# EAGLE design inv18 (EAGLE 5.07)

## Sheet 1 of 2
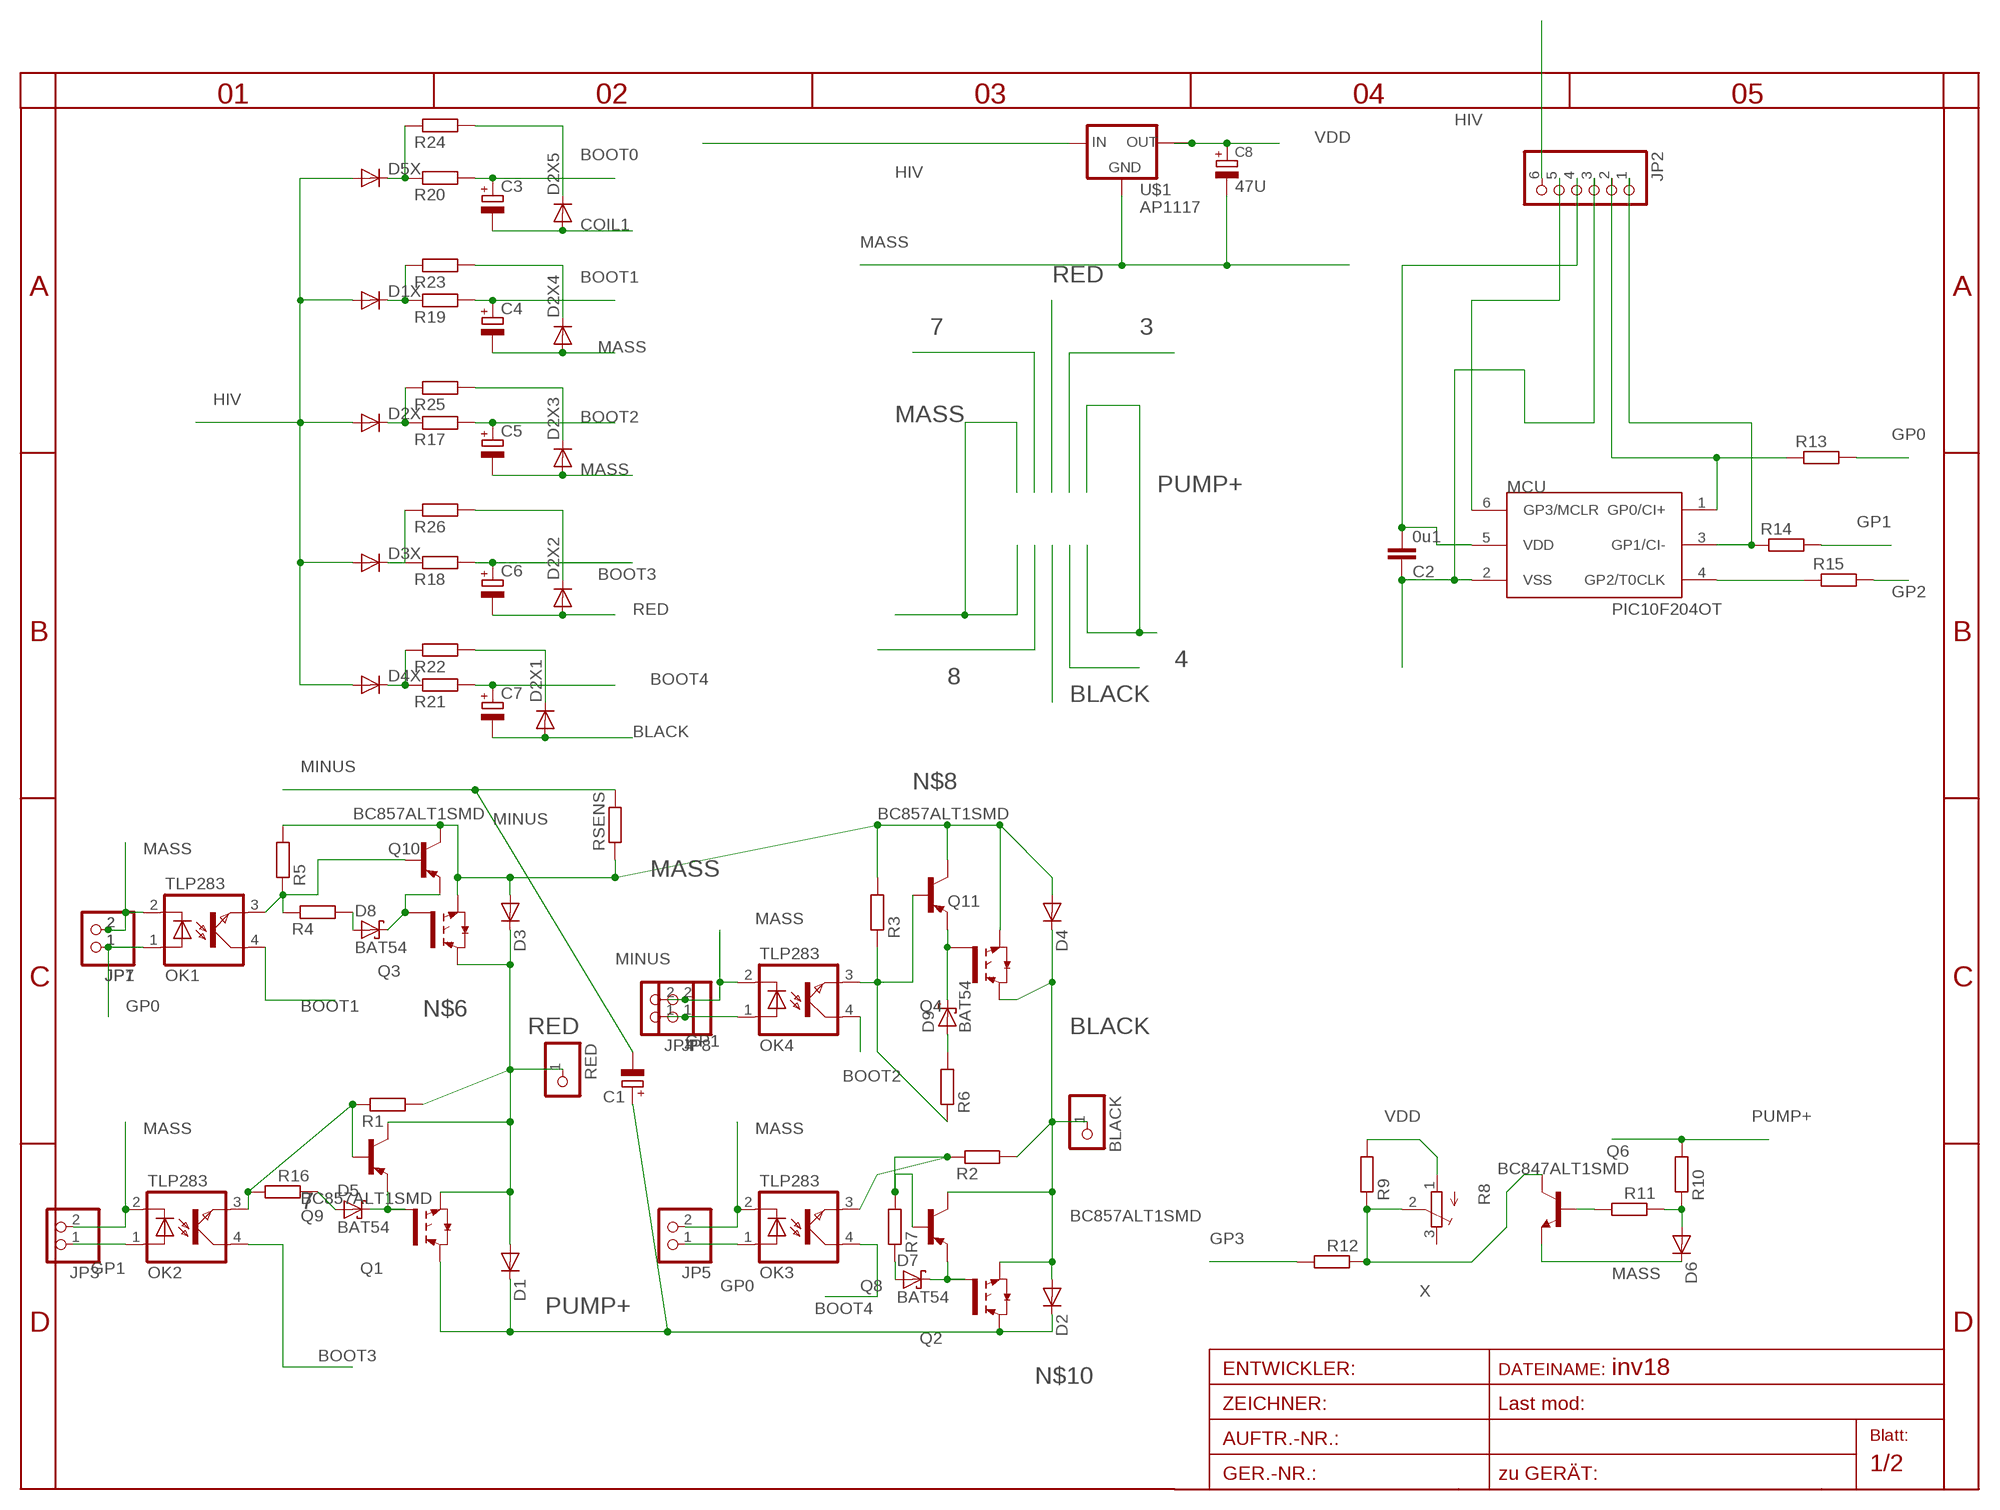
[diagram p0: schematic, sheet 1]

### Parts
BLACK  PINHD-1X14.5MM  [1X4MM5]
C1  CPOL-EUE5-13  [E5-13]
C2  0u1  C-EUC0805  [C0805]
C3  CPOL-EUC  [PANASONIC_C]
C4  CPOL-EUC  [PANASONIC_C]
C5  CPOL-EUC  [PANASONIC_C]
C6  CPOL-EUC  [PANASONIC_C]
C7  CPOL-EUC  [PANASONIC_C]
C8  47U  CPOL-EUC  [PANASONIC_C]
D1  DIODE-SMC  [SMC]
D1X  DIODE-SMA-DO214  [SMA-DO214AC]
D2  DIODE-SMC  [SMC]
D2X  DIODE-SMA-DO214  [SMA-DO214AC]
D2X1  DIODE-MINIMELF  [MINIMELF]
D2X2  DIODE-MINIMELF  [MINIMELF]
D2X3  DIODE-MINIMELF  [MINIMELF]
D2X4  DIODE-MINIMELF  [MINIMELF]
D2X5  DIODE-MINIMELF  [MINIMELF]
D3  DIODE-SMC  [SMC]
D3X  DIODE-SMA-DO214  [SMA-DO214AC]
D4  DIODE-SMC  [SMC]
D4X  DIODE-SMA-DO214  [SMA-DO214AC]
D5  BAT54  [SOT23]
D5X  DIODE-SMA-DO214  [SMA-DO214AC]
D6  DIODE-MINIMELF  [MINIMELF]
D7  BAT54  [SOT23]
D8  BAT54  [SOT23]
D9  BAT54  [SOT23]
JP1  PINHD-1X2STR  [1X02]
JP2  PINHD-1X6  [1X06BOX]
JP3  PINHD-1X2STR  [1X02]
JP4  PINHD-1X2STR  [1X02]
JP5  PINHD-1X2STR  [1X02]
JP7  PINHD-1X2STR  [1X02]
JP8  PINHD-1X2STR  [1X02]
MCU  PIC10F204OT  [SOT23-6]
OK1  TLP283  [MINI-FLAT-4]
OK2  TLP283  [MINI-FLAT-4]
OK3  TLP283  [MINI-FLAT-4]
OK4  TLP283  [MINI-FLAT-4]
Q1  IRG4BC15UD-S  [D2PACK]
Q2  IRG4BC15UD-S  [D2PACK]
Q3  IRG4BC15UD-S  [D2PACK]
Q4  IRG4BC15UD-S  [D2PACK]
Q6  BC847ALT1SMD  [SOT23]
Q8  BC857ALT1SMD  [SOT23-BEC]
Q9  BC857ALT1SMD  [SOT23-BEC]
Q10  BC857ALT1SMD  [SOT23-BEC]
Q11  BC857ALT1SMD  [SOT23-BEC]
R1  R-EU_R1206  [R1206]
R2  R-EU_R1206  [R1206]
R3  R-EU_R1206  [R1206]
R4  R-EU_R1206  [R1206]
R5  R-EU_R1206  [R1206]
R6  R-EU_R1206  [R1206]
R7  R-EU_R1206  [R1206]
R8  TRIM_EU-3223W  [3223W]
R9  R-EU_R1206  [R1206]
R10  R-EU_R1206  [R1206]
R11  R-EU_R1206  [R1206]
R12  R-EU_R1206  [R1206]
R13  R-EU_0207/25  [0207/25]
R14  R-EU_0207/25  [0207/25]
R15  R-EU_0207/25  [0207/25]
R16  R-EU_R1206  [R1206]
R17  R-EU_R1206  [R1206]
R18  R-EU_R1206  [R1206]
R19  R-EU_R1206  [R1206]
R20  R-EU_R1206  [R1206]
R21  R-EU_R1206  [R1206]
R22  R-EU_R1206  [R1206]
R23  R-EU_R1206  [R1206]
R24  R-EU_R1206  [R1206]
R25  R-EU_R1206  [R1206]
R26  R-EU_R1206  [R1206]
RED  PINHD-1X14.5MM  [1X4MM5]
RSENS  R-EU_CERAM50  [CERAM50]
U$1  AP1117  [SOT223]

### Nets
3: OK1.3(EMIT) Q10.B R4.1 R5.1
4: OK3.3(EMIT) Q8.B R2.1 R7.2
7: OK2.3(EMIT) Q9.B R1.1 R16.2
BLACK: BLACK.1 C7.- D2.A D2X1.A D4.C Q2.3(E) Q4.2(C) Q8.C R2.2
BOOT0: C3.+ R20.2 ; also sheet 2
BOOT1: C4.+ OK1.4(COL) R19.2
BOOT2: C5.+ OK4.4(COL) R17.2
BOOT3: C6.+ OK2.4(COL) R18.2
BOOT4: C7.+ OK3.4(COL) R21.2
COIL1: C3.- D2X5.A ; also sheet 2
GP0: JP1.1 JP5.1 JP7.1 OK1.1(A) OK3.1(A) R13.2
GP0I: JP2.2 MCU.1(GP0/CI+) R13.1
GP1: JP3.1 JP4.1 JP8.1 OK2.1(A) OK4.1(A) R14.2
GP1I: JP2.1 MCU.3(GP1/CI-) R14.1
GP2: R15.2 ; also sheet 2
GP2I: MCU.4(GP2/T0CLK) R15.1
GP3: JP2.5 MCU.6(GP3/MCLR) R12.2
HIV: D1X.A D2X.A D3X.A D4X.A D5X.A JP2.6 U$1.3(IN) ; also sheet 2
MASS: C2.1 C4.- C5.- C8.- D2X3.A D2X4.A D3.A D4.A D6.C JP1.2 JP2.3 JP3.2 JP4.2 JP5.2 JP7.2 JP8.2 MCU.2(VSS) OK1.2(C) OK2.2(C) OK3.2(C) OK4.2(C) Q3.3(E) Q4.3(E) Q6.2(E) Q10.C Q11.C R3.2 R5.2 RSENS.1 U$1.1(GND) ; also sheet 2
MINUS: C1.- RSENS.2 ; also sheet 2
N$2: D8.1(A) R4.2
N$4: D6.A R10.1 R11.1
N$5: Q6.1(B) R11.2
N$6: D8.3(C) Q3.1(G) Q10.E
N$7: D9.3(C) Q4.1(G) Q11.E
N$8: OK4.3(EMIT) Q11.B R3.1 R6.1
N$9: D9.1(A) R6.2
N$10: D7.3(C) Q2.1(G) Q8.E
N$11: D7.1(A) R7.1
N$12: D5.1(A) R16.1
N$13: D3X.K(C) R18.1 R26.1
N$14: D5.3(C) Q1.1(G) Q9.E
N$15: D4X.K(C) R21.1 R22.1
N$16: D2X.K(C) R17.1 R25.1
N$17: D1X.K(C) R19.1 R23.1
N$18: D5X.K(C) R20.1 R24.1
N$19: D2X1.C R22.2
N$20: D2X5.C R24.2
N$21: D2X4.C R23.2
N$22: D2X2.C R26.2
N$23: D2X3.C R25.2
PUMP+: C1.+ D1.C D2.C Q1.2(C) Q2.2(C) R10.2 ; also sheet 2
RED: C6.- D1.A D2X2.A D3.C Q1.3(E) Q3.2(C) Q9.C R1.2 RED.1
VDD: C2.2 C8.+ JP2.4 MCU.5(VDD) R8.1(A) R9.2 U$1.2(OUT) U$1.4(TAB)
X: Q6.3(C) R8.2(S) R9.1 R12.1
Unconnected: R8.3(E)

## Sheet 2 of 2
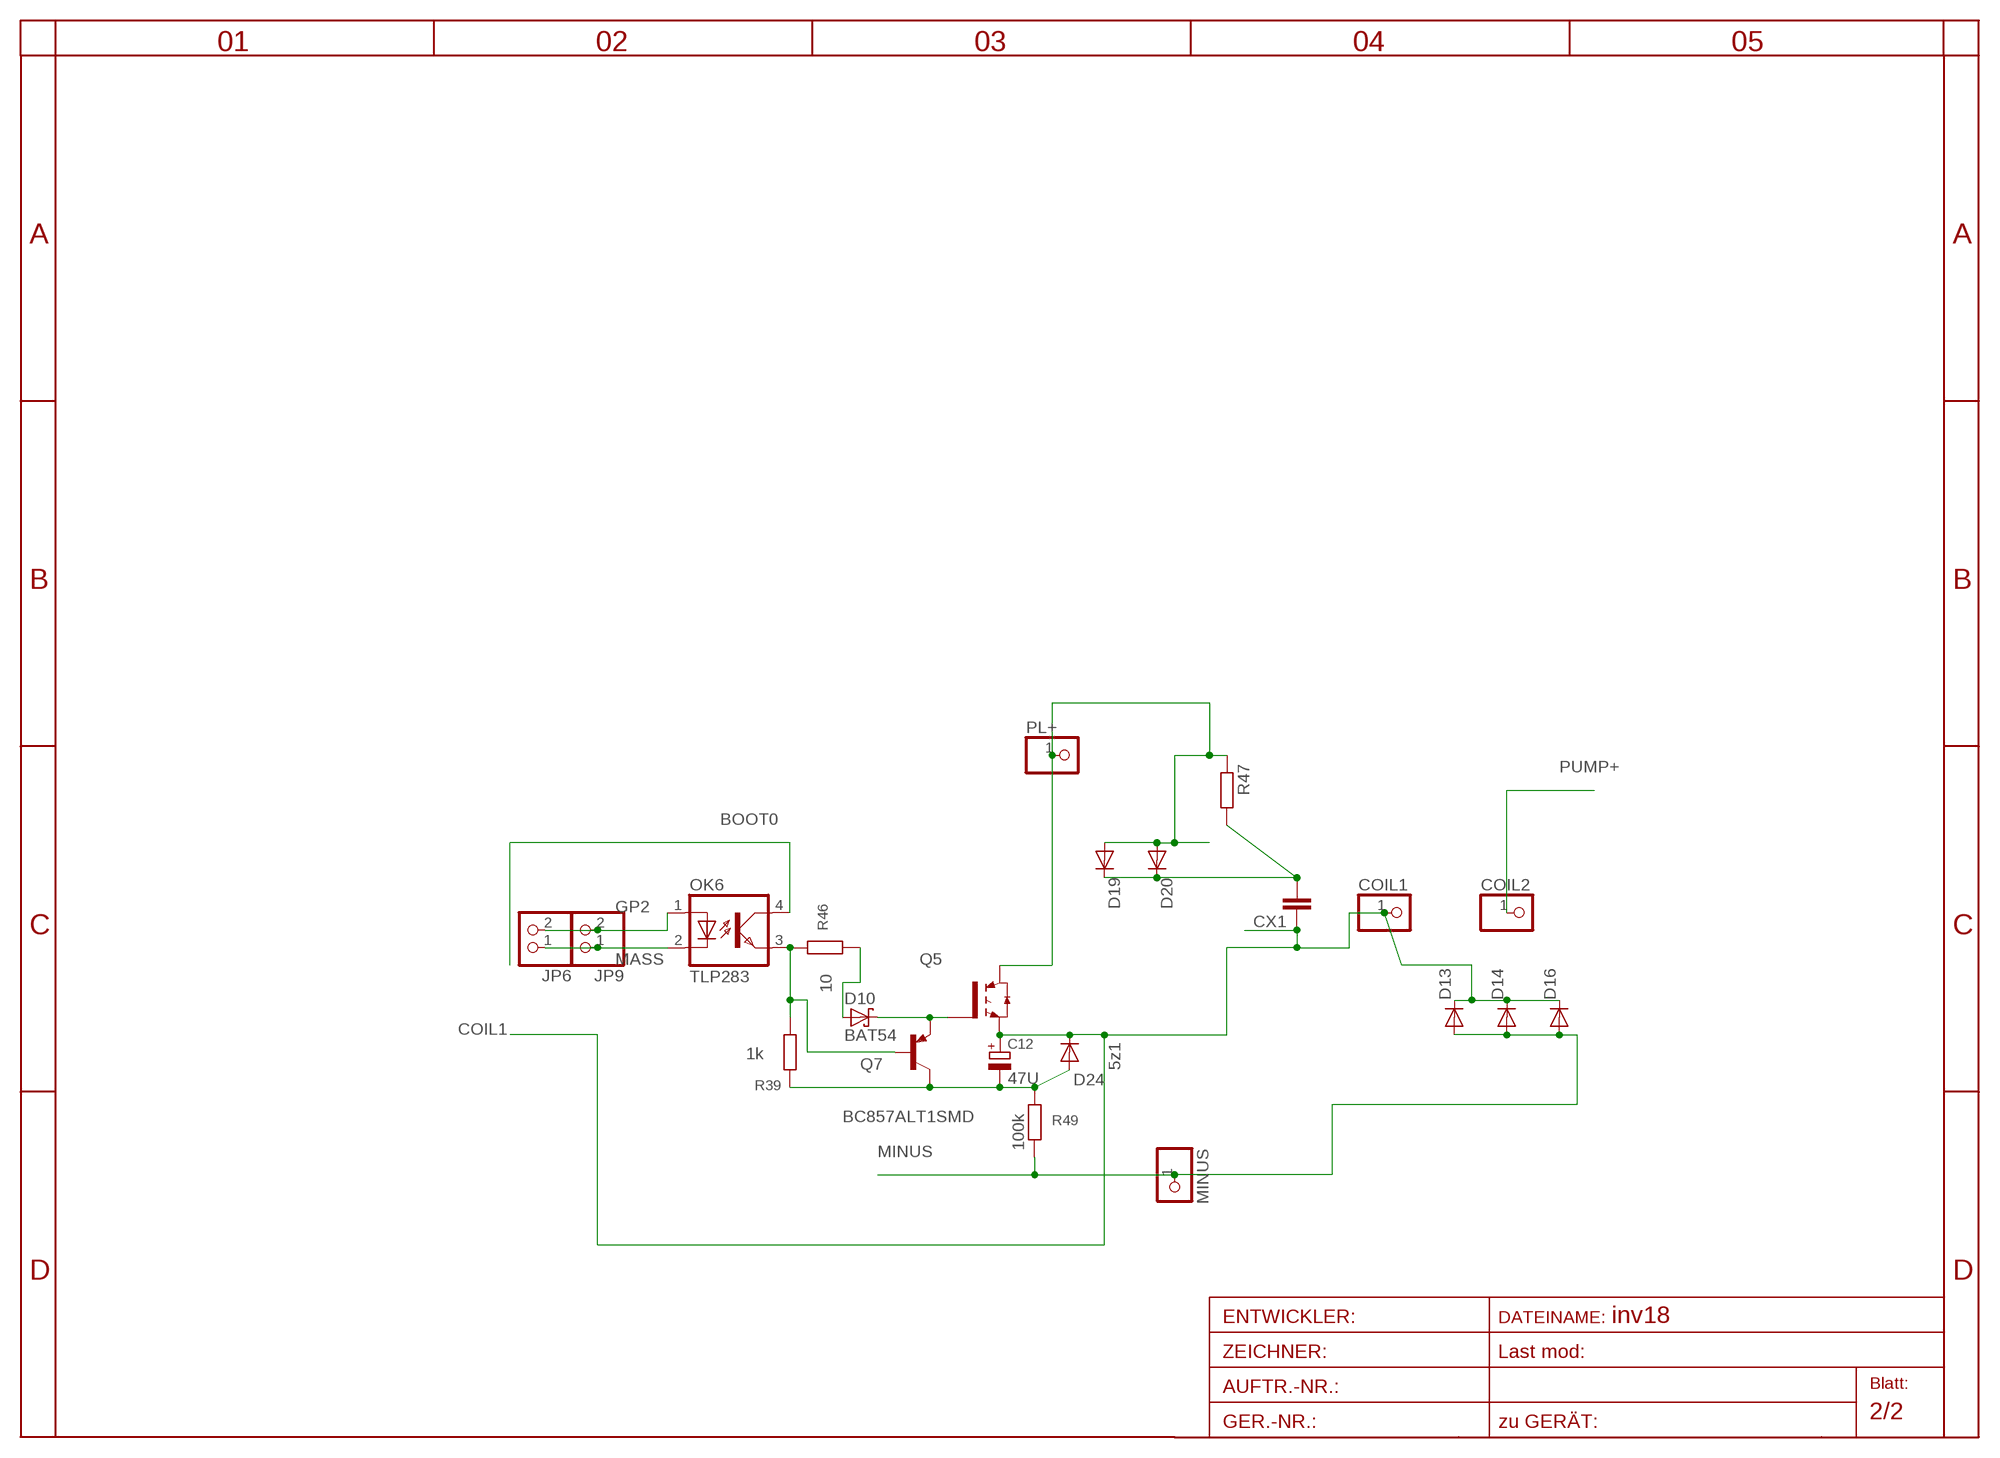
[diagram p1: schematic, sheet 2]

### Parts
C12  47U  CPOL-EUC  [PANASONIC_C]
COIL1  PINHD-1X14.5MM  [1X4MM5]
COIL2  PINHD-1X14.5MM  [1X4MM5]
CX1  CXXC22B10  [XC22B10]
D10  BAT54  [SOT23]
D13  DIODE-SMC  [SMC]
D14  DIODE-SMC  [SMC]
D16  DIODE-SMC  [SMC]
D19  DIODE-SMC  [SMC]
D20  DIODE-SMC  [SMC]
D24  5z1  DIODE-MINIMELF  [MINIMELF]
JP6  PINHD-1X2STR  [1X02]
JP9  PINHD-1X2STR  [1X02]
MINUS  PINHD-1X14.5MM  [1X4MM5]
OK6  TLP283  [MINI-FLAT-4]
PL+  PINHD-1X14.5MM  [1X4MM5]
Q5  IRG4BC15UD-S  [D2PACK]
Q7  BC857ALT1SMD  [SOT23-BEC]
R39  1k  R-EU_R1206  [R1206]
R46  10  R-EU_R1206  [R1206]
R47  R-EU_0207/5V  [0207/5V]
R49  100k  R-EU_R1206  [R1206]

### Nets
BATT-: C12.- D24.A Q7.C R39.1 R49.2
BOOT0: OK6.4(COL) ; also sheet 1
COIL1: C12.+ COIL1.1 CX1.1 D13.C D14.C D16.C D24.C Q5.3(E) ; also sheet 1
GP2: JP6.2 JP9.2 OK6.1(A) ; also sheet 1
HIV: D19.A D20.A PL+.1 Q5.2(C) R47.1 ; also sheet 1
MASS: JP6.1 JP9.1 OK6.2(C) ; also sheet 1
MINUS: D13.A D14.A D16.A MINUS.1 R49.1 ; also sheet 1
N$1: D10.3(C) Q5.1(G) Q7.E
N$3: D10.1(A) R46.1
N$43: OK6.3(EMIT) Q7.B R39.2 R46.2
PUMP+: COIL2.1 ; also sheet 1
SNUB: CX1.2 D19.C D20.C R47.2

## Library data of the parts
BLACK COIL1 COIL2 MINUS PL+ RED = pinhead:PINHD-1X1: PIN HEADER
C1 C3-C7 = rcl:CPOL-EU: POLARIZED CAPACITOR, European symbol
C2 = rcl:C-EU: CAPACITOR, European symbol
C8 C12 = rcl-2:CPOL-EU: POLARIZED CAPACITOR, European symbol
CX1 = rcl:CX: X CAPACITOR
D1 D1X D2 D2X D2X1-D2X5 D3 D3X D4 D4X D5X D6 D13 D14 D16 D19 D20 D24 = diode:DIODE-: DIODE
D5 D7-D10 = diode:BAT54: Schottky Diodes
JP1 JP3-JP9 = pinhead:PINHD-1X2: PIN HEADER
JP2 = pinhead:PINHD-1X6: PIN HEADER
MCU = microchip-3:PIC10F2*: uPC nW 0,25/0,5k Program Flash memory Comparator
OK1-OK4 OK6 = optocoupler:TLP283: TOSHIBA PHOTOCOUPLER GaAs IRED & PHOTO-TRANSISTOR Source: http://www.semicon.toshiba.co.jp/td/en/Opto/Photocoupler/en_20050928_TLP283_datasheet.pdf
Q1-Q5 = transistor-power:IRG4BC15UD-: INSULATED GATE BIPOLAR TRANSISTOR WITH ULTRAFAST SOFT RECOVERY DIODE
Q6 = transistor-npn:BC847*: NPN Transistor
Q7-Q11 = transistor-pnp:BC857*: PNP Transistror
R1-R7 R9-R12 R16-R26 R47 RSENS = rcl:R-EU_: RESISTOR, European symbol
R8 = pot:TRIM_EU-: POTENTIOMETER
R13-R15 R39 R46 R49 = rcl-2:R-EU_: RESISTOR, European symbol
U$1 = v-reg:AP1117

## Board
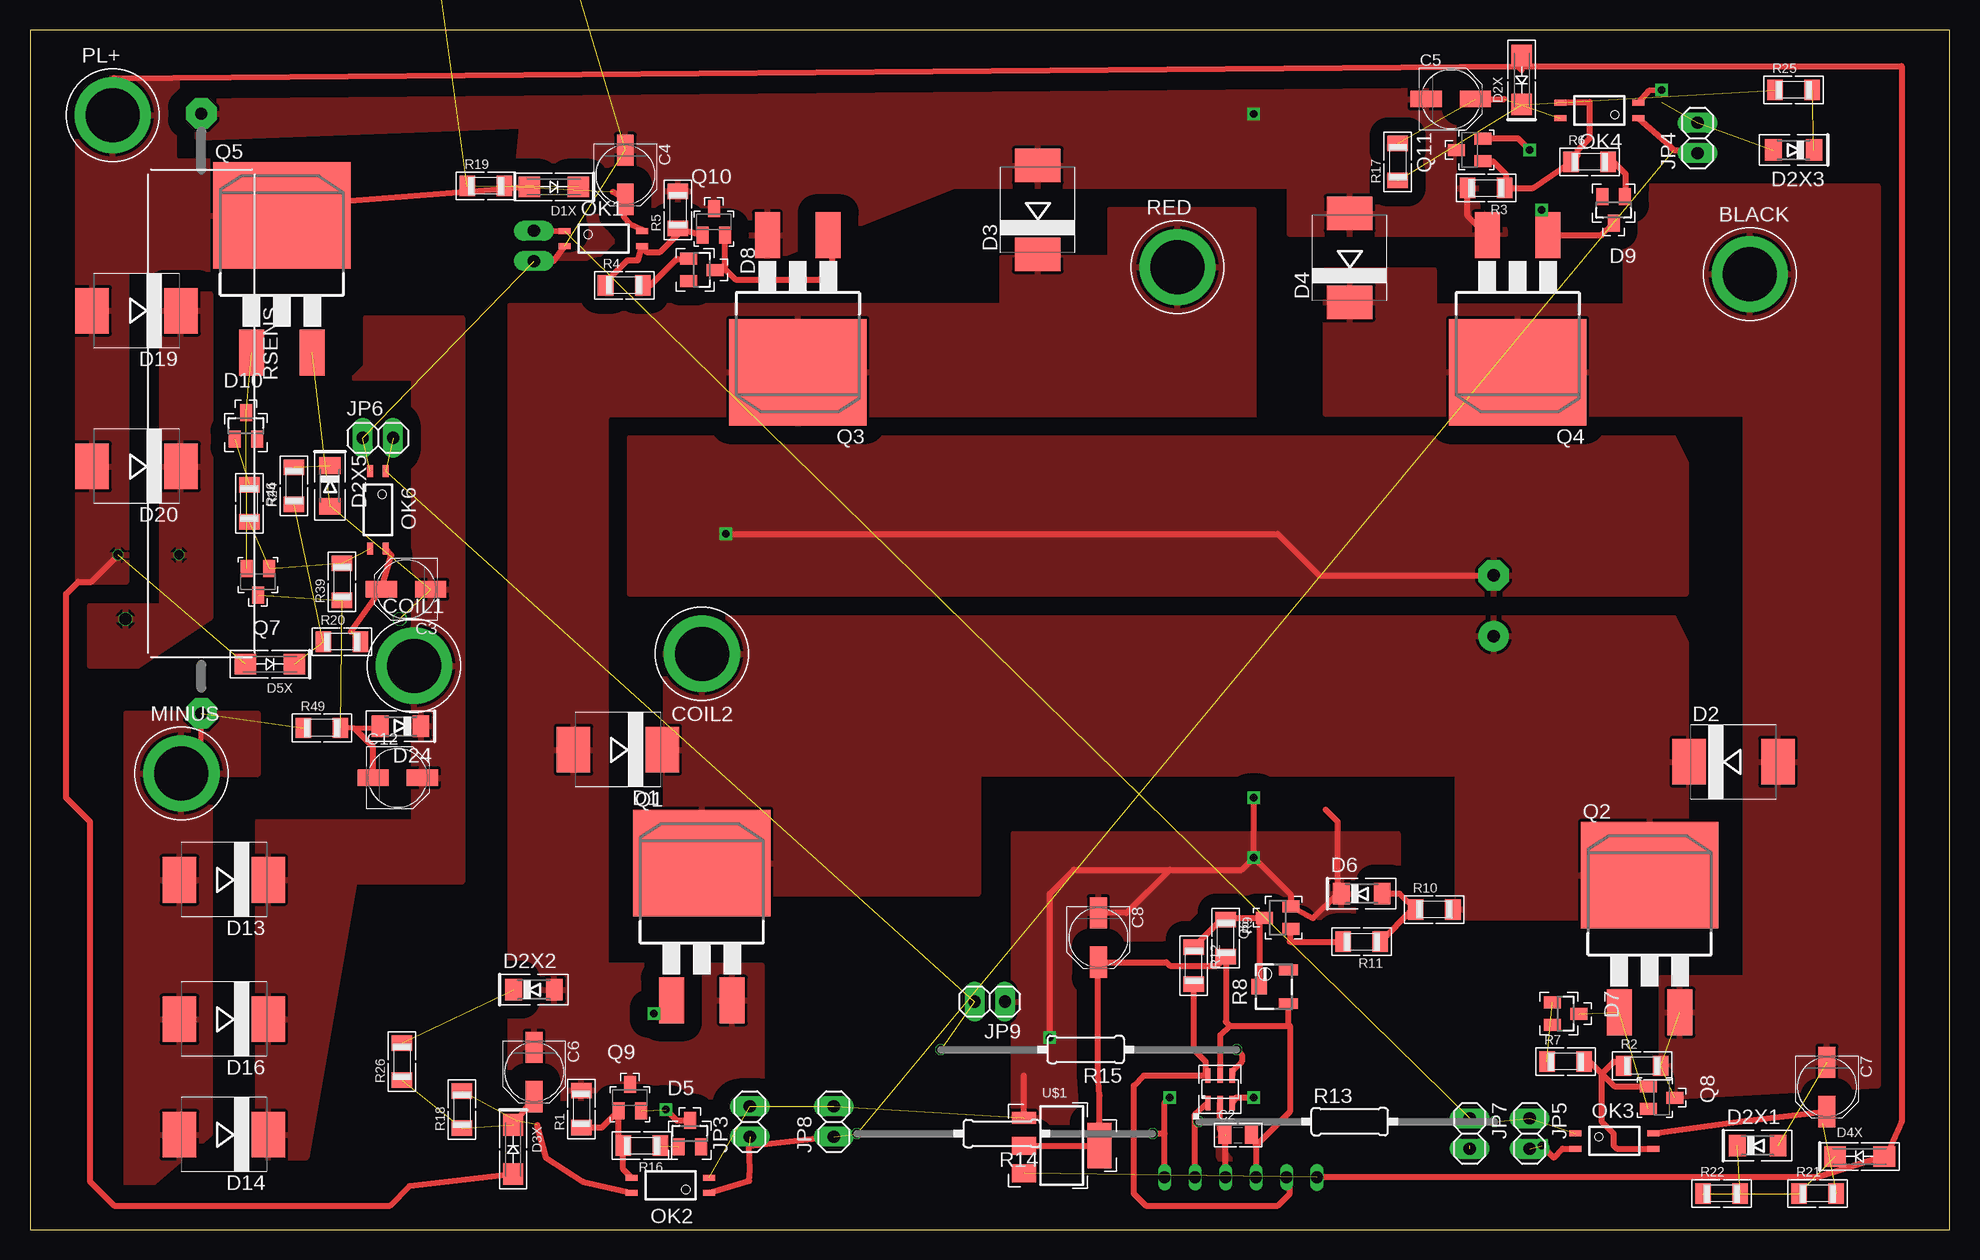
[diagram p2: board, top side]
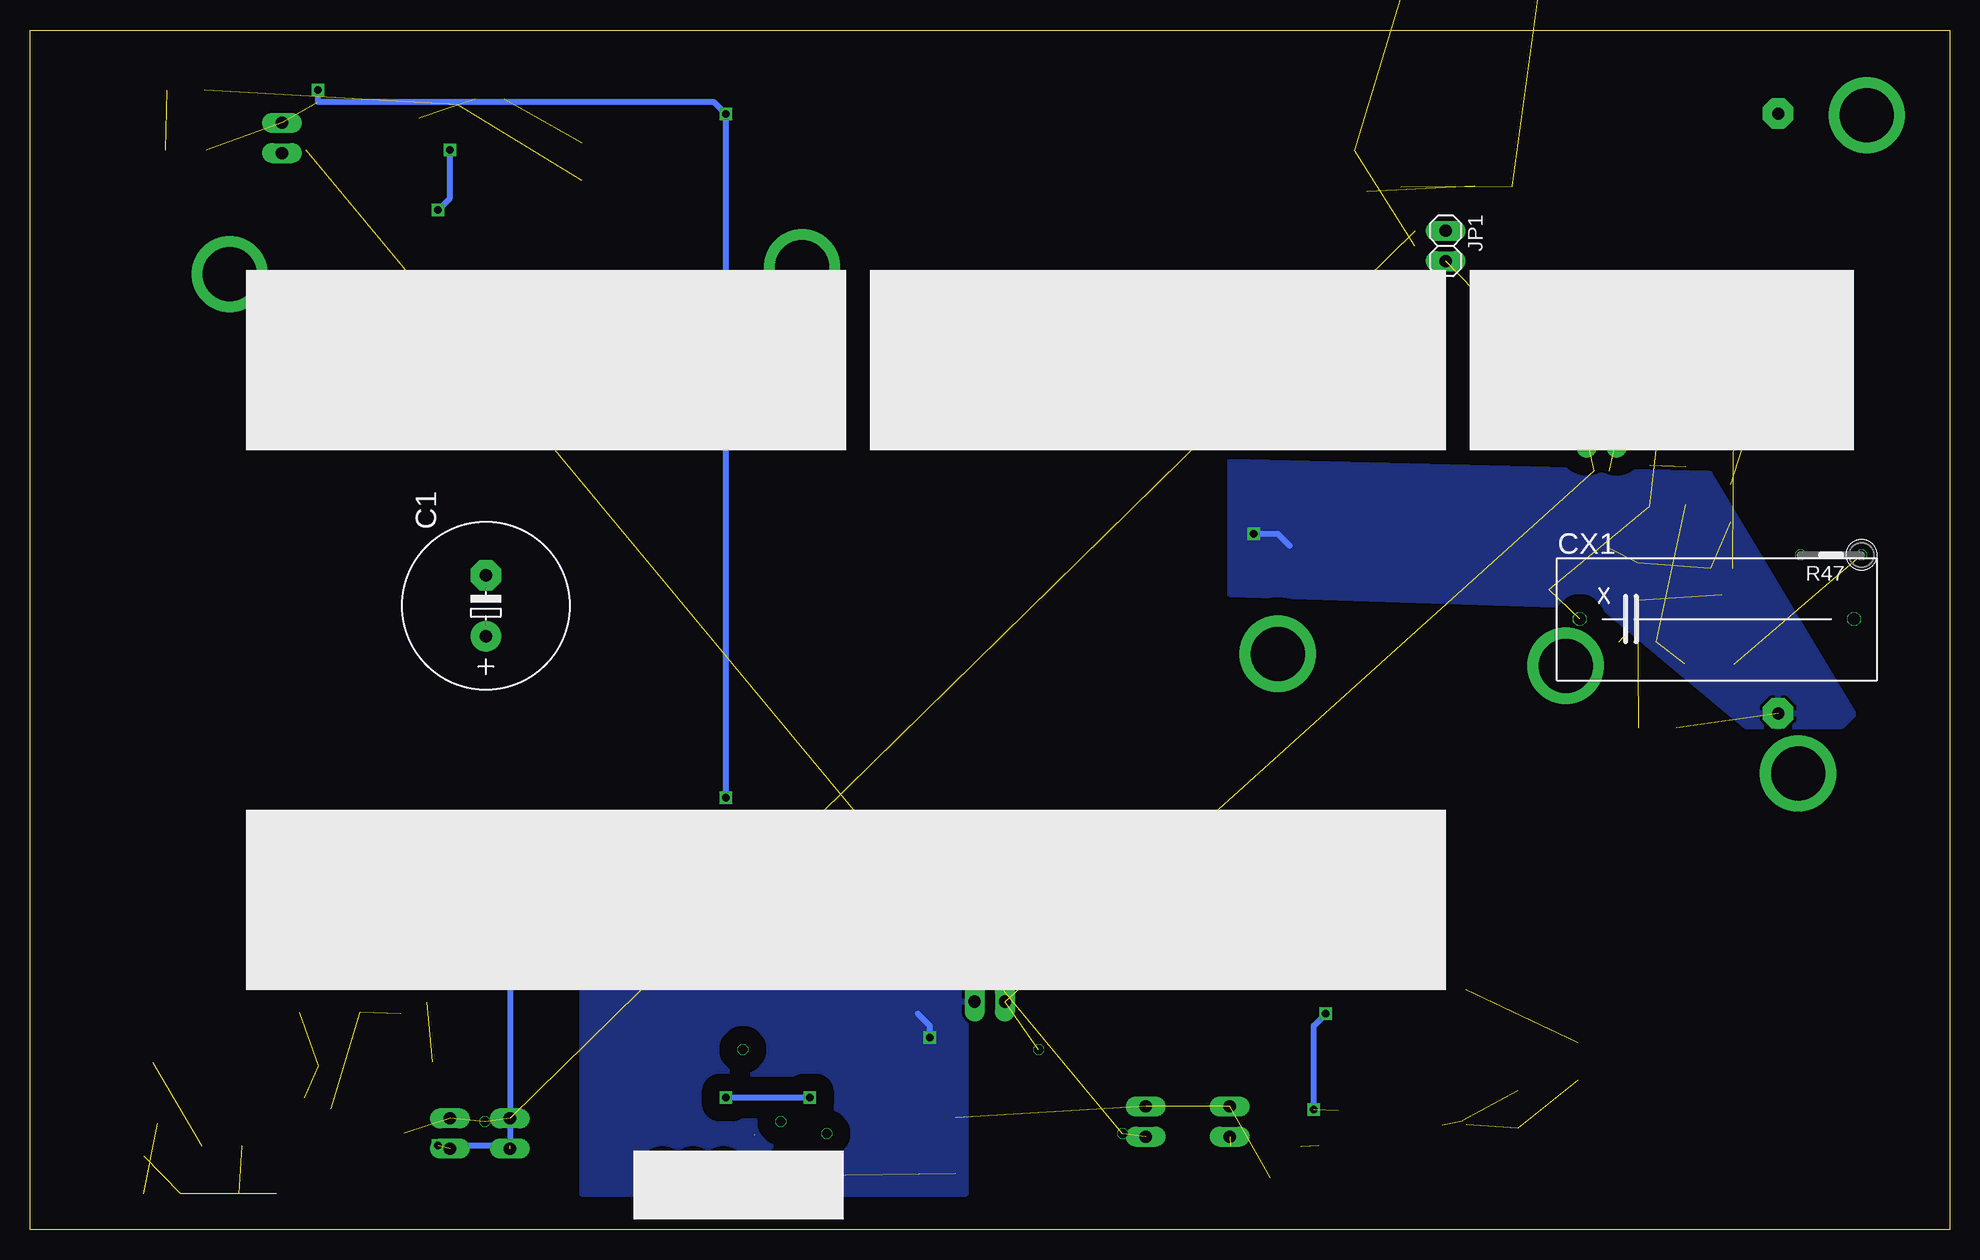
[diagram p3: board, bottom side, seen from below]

Size 160 x 100 mm. Coordinates in mm from the lower left corner, seen from the top.
Outline: 0,0 160,0 160,100 0,100 0,0
Copper layers (1*16): Top 0.035mm / dielectric 1.5mm / Bottom 0.035mm
Design rules "default": minimum track width 10mil, minimum drill 20mil, track to track 8mil, track to pad 8mil, pad to pad 8mil, via to via 8mil, smd to smd 8mil, copper to edge 40mil, drill to drill 8mil, minimum pad ring 1mil, minimum via ring 8mil, stop-mask expansion 4mil, vias tented up to drill 0mil, thermal gap 10mil

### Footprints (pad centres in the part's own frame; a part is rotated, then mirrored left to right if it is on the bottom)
1X4MM5 = drill 4.5 pad 6.35 round: 1 0,0
E5-13 = drill 1.016 pad 2.54 round: + -2.54,0 | drill 1.016 pad 2.54 octagon: - 2.54,0
C0805 = smd 1.1 x 1.5: 1 -1.1,0; 2 1.1,0
PANASONIC_C = smd 2.6 x 1.4: + 2.05,0; - -2.05,0
XC22B10 = drill 1.016 octagon: 1 -11.43,0.025; 2 11.43,0.025
SMC = smd 2.8 x 3.8: A 3.7,0; C -3.7,0
SMA-DO214AC = smd 1.8 x 1.7: A 2.05,-0.127; K -2.05,-0.127
MINIMELF = smd 1.4 x 1.8: A 1.7,0; C -1.7,0
SOT23 = smd 1 x 1.4: 1 -0.95,-1.1; 2 0.95,-1.1; 3 0,1.1
1X02 = drill 1.016 pad 1.676 long: 1 -1.27,0; 2 1.27,0
1X06BOX = drill 1 long: 1 -6.35,0; 2 -3.81,0; 3 -1.27,0; 4 1.27,0; 5 3.81,0 | drill 1.016 long: 6 6.35,0
SOT23-6 = smd 0.45 x 1.2: 1 -1.016,-1.15; 2 0,-1.15; 3 1.016,-1.15; 4 1.016,1.15; 5 0,1.15; 6 -1.016,1.15
MINI-FLAT-4 = smd 1 x 0.5: 1 -3.24,0.635; 2 -3.24,-0.635; 3 3.24,-0.635; 4 3.24,0.635
D2PACK = smd 2.083 x 3.81: 1 -2.54,-8.89; 3 2.54,-8.89 | smd 11.43 x 8.89: 2 0,2.54
SOT23-BEC = smd 1 x 1.4: B -0.95,-1.1; C 0,1.1; E 0.95,-1.1
R1206 = smd 1.3 x 1.7: 1 -1.55,0; 2 1.55,0
3223W = smd 0.9 x 1.6: 1 -1.4,-1.215; 3 1.4,-1.215 | smd 1.3 x 1.3: 2 0,1.215
0207/25 = drill 0.813 octagon: 1 -12.58,0; 2 12.08,0
0207/5V = drill 0.813 octagon: 1 -2.54,0; 2 2.54,0
CERAM50 = drill 1 pad 2.54 octagon: 1 -25,0; 2 25,0
SOT223 = smd 1 x 2: 1 -2.3,-3.15 | smd 1.5 x 2: 2 0,-3.15; 3 2.3,-3.15 | smd 3.8 x 2: 4 0,3.15

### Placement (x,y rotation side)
BLACK  143.35,79.64 0 top
C1  122,52 90 bottom
C2  100.7,7.88 0 top
C3  31.34,53.37 180 top
C4  49.62,87.92 270 top
C5  118.43,94.25 0 top
C6  42.02,13.13 270 top
C7  149.78,11.89 270 top
C8  89.05,24.34 270 top
C12  30.65,37.66 0 top
COIL1  32,47 0 top
COIL2  56,48 180 top
CX1  19.39,50.87 0 bottom
D1  49,40 180 top
D1X  43.66,86.79 180 top
D2  142,39 0 top
D2X  124.22,95.83 90 top
D2X1  144,7 0 top
D2X2  42,20 0 top
D2X3  147,90 180 top
D2X4  not placed on the board
D2X5  25,62 270 top
D3  84,85 90 top
D3X  40.4,6.68 270 top
D4  110,81 90 top
D4X  152.51,6.22 0 top
D5  55,8 0 top
D5X  20,47 180 top
D6  111,28 0 top
D7  128,18 270 top
D8  56,80 270 top
D9  132,85 180 top
D10  18,67 0 top
D13  16.16,29.15 180 top
D14  16.16,7.91 180 top
D16  16.16,17.53 180 top
D19  8.88,76.59 180 top
D20  8.88,63.62 180 top
D24  30.89,41.96 180 top
JP1  42,82 270 bottom
JP2  100.93,4.35 180 bottom
JP3  60,9 90 top
JP4  139,91 90 top
JP5  125,8 270 top
JP6  29,66 0 top
JP7  120,8 270 top
JP8  67,9 90 top
JP9  80,19 180 top
MCU  99.2,11.7 0 top
MINUS  12.62,38.02 0 top
OK1  47.8,82.6 0 top
OK2  53.38,3.68 180 top
OK3  132.06,7.38 0 top
OK4  130.81,93.29 180 top
OK6  29,60 270 top
PL+  6.89,92.9 0 top
Q1  56,28 0 top
Q2  135,27 0 top
Q3  64,74 180 top
Q4  124,74 180 top
Q5  21,82 0 top
Q6  104,26 90 top
Q7  19,54 180 top
Q8  136,11 270 top
Q9  50,11 0 top
Q10  57,84 0 top
Q11  120,90 90 top
R1  45.95,10.05 90 top
R2  134.38,13.65 0 top
R3  121.38,86.83 180 top
R4  49.53,78.71 0 top
R5  54,85 90 top
R6  130,89 0 top
R7  128,14 0 top
R8  103.68,20.24 90 top
R9  99.67,24.3 270 top
R10  117.05,26.67 0 top
R11  111,24 180 top
R12  97,22 270 top
R13  110,9 0 top
R14  81,8 180 top
R15  88,15 180 top
R16  51,7 180 top
R17  114,89 90 top
R18  36,10 90 top
R19  38,87 0 top
R20  26,49 0 top
R21  149,3 0 top
R22  141,3 0 top
R23  not placed on the board
R24  22,62 90 top
R25  147,95 0 top
R26  31,14 90 top
R39  26,54 90 top
R46  18.28,60.54 270 top
R47  9.88,56.24 180 bottom
R49  24.34,41.81 0 top
RED  95.65,80.23 0 top
RSENS  14.29,68.04 270 top
U$1  86,7 270 top

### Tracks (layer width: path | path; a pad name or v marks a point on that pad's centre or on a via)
3
  Top 0.5: Q10.B 54.05,83.45 R5.1 54,83 52.5,81.5 51.38,81.5 OK1.3 50.67,80.8 49.8,80.8 47.98,78.98 R4.1
4
  Top 0.5: OK3.3 132.25,6.75 132,7 132,8 131,9 131,13 | 131,13 132,14 132.48,14 R2.1 | R7.2 130,14 131,13 | Q8.B 132.05,11.95 131,13
7
  Top 0.5: R1.1 47.65,8.5 Q9.B 49.05,7.4 R16.2 49.45,5 OK2.3
BATT-  (2 unrouted)
  Top 0.406: R49.2 27,41.81 29.04,41.81 D24.A
  Top 0.5: C12.- 28.6,40.21 27,41.81
BLACK  (3 unrouted)
  pour Top (isolate 1.5, rank 2): 108,80 117,80 117,77 133,77 133,87 154,87 154,12 136,11 136,21 143,21 143,68 108,68
BOOT0  (1 unrouted)
  Top 0.5: 26.76,49.84 C3.+ 30.11,56.2 OK6.4
BOOT1  (1 unrouted)
  Top 0.5: 48.57,86.52 C4.+ 49.53,84.37 50,83.8 51,83.36 OK1.4
BOOT2  (2 unrouted)
  Top 0.5: C5.+ 122.88,94.25
BOOT3  (2 unrouted)
  Top 0.5: 40.62,9.08 C6.+ | 42.27,8.73 43,6 46.09,4 OK2.4
BOOT4  (1 unrouted)
  Top 0.5: 149.39,8.84 C7.+ 142.6,9.02 OK3.4
COIL1  (3 unrouted)
  pour Top (isolate 1.5, rank 2): 28,76 36,76 36,29 27,29 23,6 19,6 19,34 32,34 32,71 27,71 28,72
GP0  (4 unrouted)
  Top 0.5: JP1.1 43.62,83.27 OK1.1
GP0I
  Top 0.5: JP2.2 97.12,9 | 97.12,9 97.12,9.62 MCU.1 | 97.12,9 R13.1
GP1  (3 unrouted)
  Top 0.5: OK2.1 59.95,4.04 60,5 59.92,7 R14.2 | OK4.1 136.34,90.66 137,90 138.73,90 JP4.1
GP1I  (via drill 0.6)
  Top 0.5: JP2.1 94.58,8 | 94.58,8 94.58,10.58 v95,11 | v102,11 100.53,11 MCU.3 | 94.58,8 R14.1
  Bottom 0.5: v95,11 v102,11
GP2  (3 unrouted)
GP2I
  Top 0.5: MCU.4 100.22,13.22 101,14 101,14.58 R15.1
GP3
  Top 0.5: R12.2 97,15 98,14 98,12.9 MCU.6 92.85,12.85 92,12 92,3 93,2 104,2 105,3 105,4.09 JP2.5
HIV  (2 unrouted)
  Top 0.5: 124,97 156,97 156,9 154.44,5.44 D4X.A 149,4.35 JP2.6 | 7,96 124,97 | D1X.A 21.85,85.39 Q5.2 | D2X.A 124.35,96.65 124,97 | D3X.A 31.63,3.63 30,2 7,2 5,4 5,34 3,36 3,53 4,54 5.1,54 R47.1
  pour Top (isolate 1.5, rank 2): 4,96 17,96 17,80 8,80 8,54 4,54
MASS  (via drill 0.6)  (12 unrouted)
  Top 0.5: JP2.3 99.66,7.84 99.2,8.3 MCU.2 | U$1.1 82.85,12.85 | 108,35 109,34 109,28.3 D6.C 109,28 106.95,25.95 Q6.2 105.1,27.9 v102,31 | OK4.2 134.93,94.92 v136,95 | v102,31 v102,36 | OK3.2 127.75,6.75 127,6 v126,7 | C8.- 91.39,26.39 95,30 | 95,30 101,30 v102,31 | v85,16 85,28 87,30 95,30 | JP1.2 43.66,80.73 OK1.2 | R3.2 119.83,84.52 Q4.3
  Bottom 0.5: v102,36 v102,93 103,94 136,94 v136,95 | v85,16 85,17 86,18 | 102,30 v102,31 119,31 120,30 120,7 v126,7
  pour Top (isolate 1.5): 14,95 118,97 123,83 105,83 105,87 77,87 62,81 44,81 40,82 41,92 14,91
  pour Bottom (isolate 1.5, rank 2): 82,33 114,33 114,3 82,3
  pour Top (isolate 1.5, rank 2): 82,33 114,33 114,3 82,3
MINUS  (via drill 0.6)  (1 unrouted)
  Top 0.406: RSENS.2 14.29,39.69 MINUS.1
  Top 0.5: C1.- 107.46,54.54 104,58 v58,58
  Bottom 0.5: v58,58 56,58 55,57
  pour Top (isolate 1.5): 138,53 50,53 50,66 137,66 138,64
  pour Top (isolate 1.5, rank 3): 8,43 8,2 15,8 15,38 19,38 19,43
  pour Bottom (isolate 1.5, rank 2): 8,43 20,63 60,64 60,53 29,52 17,42 9,42
N$1  (2 unrouted)
N$2
  Top 0.5: R4.2 51.71,78.71 53.9,80.9 54.85,80.9 D8.1
N$3  (1 unrouted)
N$4
  Top 0.5: R11.1 115.22,26.67 R10.1 114.17,28 D6.A
N$5
  Top 0.5: R11.2 105,24 105,24.95 Q6.1
N$6
  Top 0.5: 57.6,80 58,80 58.8,79.2 65.8,79.2 66.9,80.3 66.9,82.53 Q3.1 | D8.3 57.6,80 | Q10.E 57.95,80.35 57.6,80
N$7  (via drill 0.6)
  Top 0.5: Q11.E 124.05,90.95 v125,90 | v126,85 126,83.43 Q4.1 130.99,82.89 D9.3
  Bottom 0.5: v125,90 125,86 v126,85
N$8
  Top 0.5: Q11.B 121.95,89.05 123,88 123,86.9 R3.1 125.28,86.83 R6.1 129,89.55 129,90 130,91 130,94 129.93,93.92 OK4.3
N$9
  Top 0.5: R6.2 132,89 133,88 133,86.15 D9.1
N$10  (2 unrouted)
N$11  (1 unrouted)
N$12  (1 unrouted)
N$13  (2 unrouted)
N$14  (via drill 0.6)  (1 unrouted)
  Top 0.5: D5.3 53.9,9.1 v53,10 | v52,18 52.35,18 Q1.1
  Bottom 0.5: v53,10 53,17 v52,18
N$15  (2 unrouted)
N$16  (2 unrouted)
N$17  (2 unrouted)
N$18  (2 unrouted)
N$19  (1 unrouted)
N$20  (1 unrouted)
N$21  (1 unrouted)
N$22  (1 unrouted)
N$23  (1 unrouted)
N$43  (3 unrouted)
PUMP+
  pour Top (isolate 1.5): 138,49 138,26 119,26 119,38 79,38 79,28 53,28 53,51 137,51
RED
  pour Top (isolate 1.5, rank 2): 102,67 102,85 90,85 90,81 81,81 81,77 40,77 40,11 61,11 61,22 48,22 48,67
SNUB
  pour Top (isolate 1.5, rank 2): 11,78 15,78 15,51 9,47 5,47 5,52 11,52
VDD
  Top 0.5: U$1.2 U$1.4 89.15,11.15 89,13 89,22.24 C8.+ 94.71,22.29 95,22 98.92,22 R9.2 99.67,17.33 100,17 | 102.2,7 JP2.4 | 102.2,7 102.2,7.33 C2.2 | MCU.5 99.2,16.2 100,17 | 100,17 105,17 | 105,17 105,9.8 102.2,7 | R8.1 104.89,17.11 105,17
X
  Top 0.5: R8.2 102.47,25.57 Q6.3 99.82,26 R9.1 99.3,25.85 R12.1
